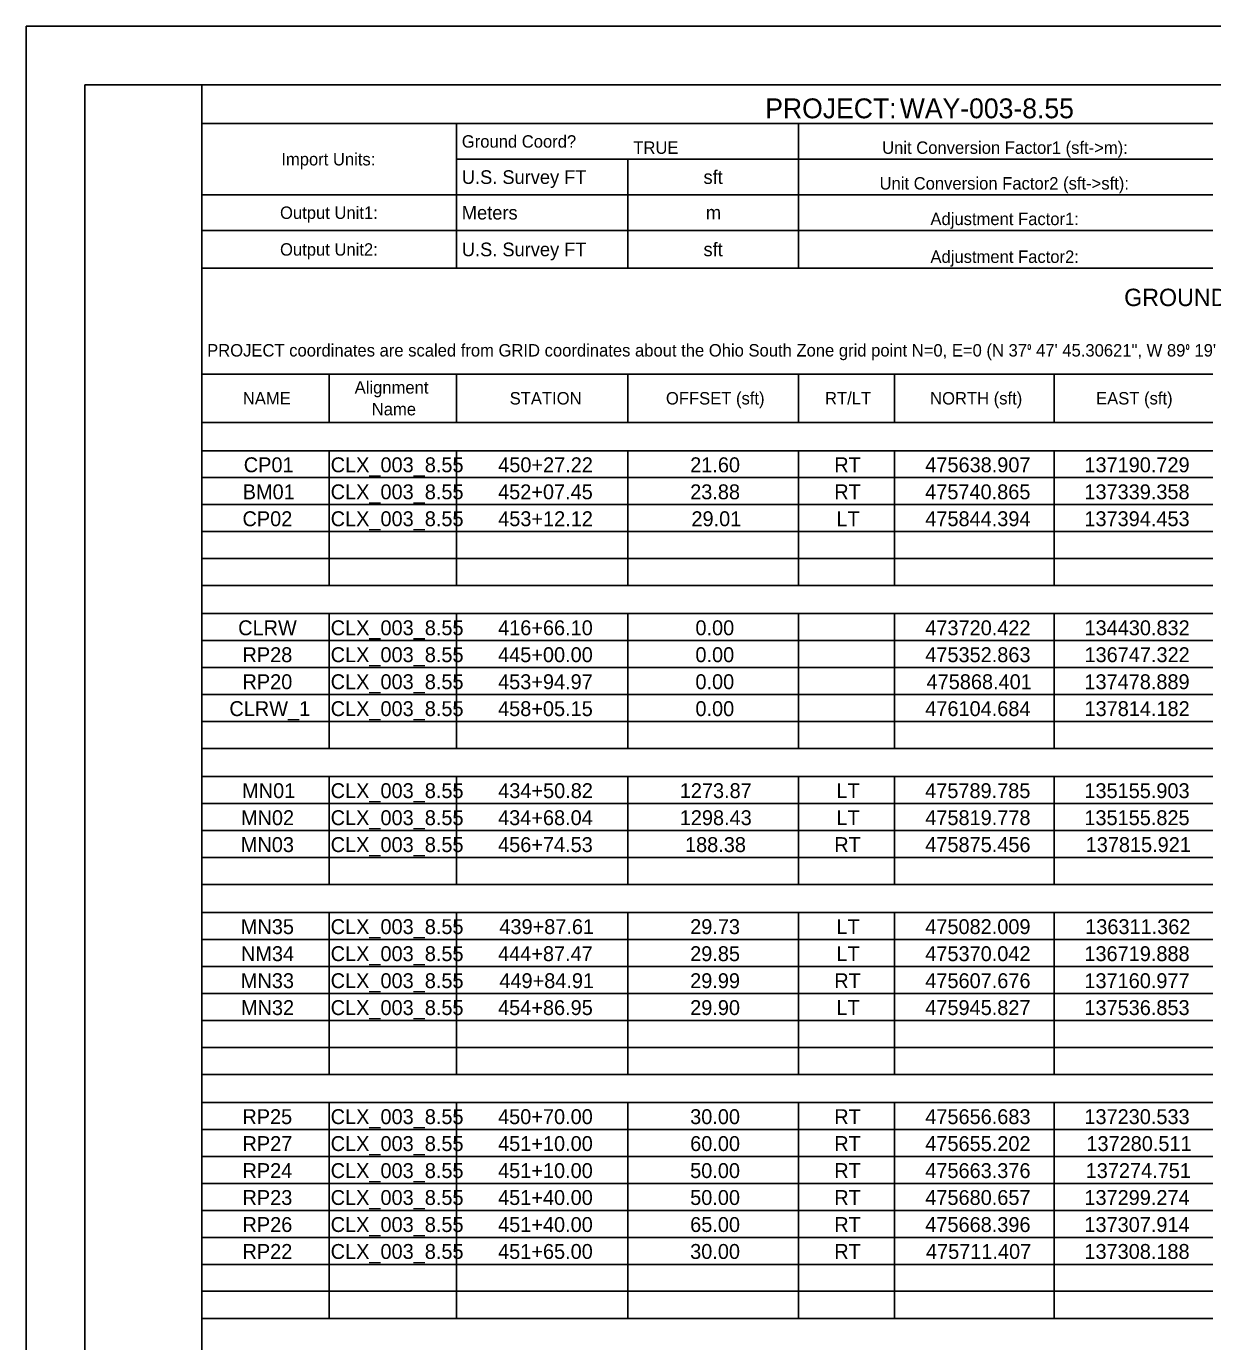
# Model space of a CAD drawing. Extents: x 0 to 34, y 0 to 22.
# Drawn here: x 0 to 10.14, y 10.76 to 22 of the extents above; entities that cross this region are included whole.
import ezdxf

# ---------------------------------------------------------------- set-up
doc = ezdxf.new("R2010")
doc.units = 0
for name, color, linetype in [('SH_Border', 7, 'Continuous'), ('SH_Cut_Line', 7, 'Continuous'), ('SH_Text', 7, 'Continuous')]:
    doc.layers.add(name, color=color, linetype=linetype)

msp = doc.modelspace()

# ---------------------------------------------------------------- linework, layer by layer
at = {"layer": 'SH_Border'}
for points in [[(0.5, 21.5), (1.5, 21.5), (1.5, 0.5), (0.5, 0.5)], [(1.5, 21.5), (33.5, 21.5), (33.5, 0.5), (1.5, 0.5)]]:
    msp.add_lwpolyline(points, close=True, dxfattribs=at)
at = {"layer": 'SH_Cut_Line'}
msp.add_lwpolyline([(0, 0), (34, 0), (34, 22), (0, 22)], close=True, dxfattribs=at)
at = {"layer": 'SH_Text'}
for p, q in [((1.5, 21.168), (10.142, 21.168)), ((1.5, 21.168), (1.5, 19.028)), ((3.677, 21.168), (3.677, 19.932)), ((6.6, 21.168), (6.6, 19.932)), ((3.677, 20.864), (10.142, 20.864)), ((5.143, 20.864), (5.143, 19.932)), ((1.5, 20.559), (6.6, 20.559)), ((6.6, 20.559), (10.142, 20.559)), ((1.5, 20.255), (10.142, 20.255)), ((1.5, 19.932), (6.6, 19.932)), ((6.6, 19.932), (10.142, 19.932)), ((1.5, 19.028), (10.142, 19.028)), ((1.5, 19.028), (1.5, 17.451)), ((2.588, 19.028), (2.588, 18.613)), ((3.677, 19.028), (3.677, 18.613)), ((5.143, 19.028), (5.143, 18.613)), ((6.6, 19.028), (6.6, 18.613)), ((7.421, 19.028), (7.421, 18.613)), ((8.786, 19.028), (8.786, 18.613)), ((1.5, 18.613), (10.142, 18.613)), ((1.5, 18.373), (10.142, 18.373)), ((2.588, 18.373), (2.588, 17.451)), ((3.677, 18.373), (3.677, 17.451)), ((5.143, 18.373), (5.143, 17.451)), ((6.6, 18.373), (6.6, 17.451)), ((7.421, 18.373), (7.421, 17.451)), ((8.786, 18.373), (8.786, 17.451)), ((1.5, 18.143), (10.142, 18.143)), ((1.5, 17.912), (10.142, 17.912)), ((1.5, 17.682), (10.142, 17.682)), ((1.5, 17.451), (10.142, 17.451)), ((1.5, 17.451), (1.5, 16.981)), ((2.588, 17.451), (2.588, 17.221)), ((3.677, 17.451), (3.677, 17.221)), ((5.143, 17.451), (5.143, 17.221)), ((6.6, 17.451), (6.6, 17.221)), ((7.421, 17.451), (7.421, 17.221)), ((8.786, 17.451), (8.786, 17.221)), ((1.5, 17.221), (10.142, 17.221)), ((1.5, 16.981), (10.142, 16.981)), ((1.5, 16.981), (1.5, 13.504)), ((2.588, 16.981), (2.588, 15.828)), ((3.677, 16.981), (3.677, 15.828)), ((5.143, 16.981), (5.143, 15.828)), ((6.6, 16.981), (6.6, 15.828)), ((7.421, 16.981), (7.421, 15.828)), ((8.786, 16.981), (8.786, 15.828)), ((1.5, 16.75), (10.142, 16.75)), ((1.5, 16.52), (10.142, 16.52)), ((1.5, 16.289), (10.142, 16.289)), ((1.5, 16.059), (10.142, 16.059)), ((1.5, 15.828), (10.142, 15.828)), ((1.5, 15.588), (10.142, 15.588)), ((2.588, 15.588), (2.588, 14.666)), ((3.677, 15.588), (3.677, 14.666)), ((5.143, 15.588), (5.143, 14.666)), ((6.6, 15.588), (6.6, 14.666)), ((7.421, 15.588), (7.421, 14.666)), ((8.786, 15.588), (8.786, 14.666)), ((1.5, 15.358), (10.142, 15.358)), ((1.5, 15.127), (10.142, 15.127)), ((1.5, 14.896), (10.142, 14.896)), ((1.5, 14.666), (10.142, 14.666)), ((1.5, 14.426), (10.142, 14.426)), ((2.588, 14.426), (2.588, 13.504)), ((3.677, 14.426), (3.677, 13.504)), ((5.143, 14.426), (5.143, 13.504)), ((6.6, 14.426), (6.6, 13.504)), ((7.421, 14.426), (7.421, 13.504)), ((8.786, 14.426), (8.786, 13.504)), ((1.5, 14.195), (10.142, 14.195)), ((1.5, 13.965), (10.142, 13.965)), ((1.5, 13.734), (10.142, 13.734)), ((1.5, 13.504), (10.142, 13.504)), ((1.5, 13.504), (1.5, 12.803)), ((2.588, 13.504), (2.588, 13.043)), ((3.677, 13.504), (3.677, 13.043)), ((5.143, 13.504), (5.143, 13.043)), ((6.6, 13.504), (6.6, 13.043)), ((7.421, 13.504), (7.421, 13.043)), ((8.786, 13.504), (8.786, 13.043)), ((1.5, 13.273), (10.142, 13.273)), ((1.5, 13.043), (10.142, 13.043)), ((1.5, 12.803), (10.142, 12.803)), ((1.5, 12.803), (1.5, 10.958)), ((2.588, 12.803), (2.588, 10.958)), ((3.677, 12.803), (3.677, 10.958)), ((5.143, 12.803), (5.143, 10.958)), ((6.6, 12.803), (6.6, 10.958)), ((7.421, 12.803), (7.421, 10.958)), ((8.786, 12.803), (8.786, 10.958)), ((1.5, 12.572), (10.142, 12.572)), ((1.5, 12.342), (10.142, 12.342)), ((1.5, 12.111), (10.142, 12.111)), ((1.5, 11.881), (10.142, 11.881)), ((1.5, 11.65), (10.142, 11.65)), ((1.5, 11.419), (10.142, 11.419)), ((1.5, 11.189), (10.142, 11.189)), ((1.5, 10.958), (10.142, 10.958))]:
    msp.add_line(p, q, dxfattribs=at)

# ---------------------------------------------------------------- texts
for s, height, p in [('PROJECT:', 0.1697, (6.317, 21.214)), ('WAY-003-8.55', 0.1697, (7.467, 21.214)), ('Ground Coord?', 0.10606, (3.723, 20.963)), ('Import Units:', 0.10606, (2.18, 20.811)), ('TRUE', 0.1061, (5.189, 20.91)), ('Unit Conversion Factor1 (sft->m):', 0.10606, (7.316, 20.91)), ('U.S. Survey FT', 0.11667, (3.723, 20.653)), ('sft', 0.1167, (5.789, 20.653)), ('Unit Conversion Factor2 (sft->sft):', 0.10606, (7.294, 20.605)), ('Output Unit1:', 0.10606, (2.169, 20.354)), ('Meters', 0.1167, (3.723, 20.349)), ('m', 0.117, (5.809, 20.349)), ('Adjustment Factor1:', 0.10606, (7.729, 20.301)), ('Output Unit2:', 0.10606, (2.169, 20.04)), ('U.S. Survey FT', 0.11667, (3.723, 20.035)), ('sft', 0.1167, (5.789, 20.035)), ('Adjustment Factor2:', 0.10606, (7.729, 19.978)), ('GROUND COORDINATES - U.S. Survey FT', 0.14849, (9.385, 19.609)), ('PROJECT coordinates are scaled from GRID coordinates about the Ohio South Zone grid point N=0, E=0 (N 37⁰ 47\' 45.30621", W 89⁰ 19\' 00.02517")', 0.106063, (1.546, 19.178)), ('Alignment ', 0.1061, (2.807, 18.861)), ('NAME', 0.1061, (1.851, 18.768)), ('Name', 0.1061, (2.953, 18.675)), ('STATION', 0.1061, (4.132, 18.768)), ('OFFSET (sft)', 0.10606, (5.468, 18.768)), ('RT/LT', 0.1061, (6.828, 18.768)), ('NORTH (sft)', 0.10606, (7.726, 18.768)), ('EAST (sft)', 0.1061, (9.145, 18.768)), ('CP01', 0.1273, (1.859, 18.189)), ('CLX_003_8.55', 0.12728, (2.602, 18.189)), ('450+27.22', 0.1273, (4.034, 18.189)), ('21.60', 0.1273, (5.675, 18.189)), ('RT', 0.1273, (6.907, 18.189)), ('475638.907', 0.1273, (7.685, 18.189)), ('137190.729', 0.1273, (9.045, 18.189)), ('BM01', 0.1273, (1.85, 17.958)), ('CLX_003_8.55', 0.12728, (2.602, 17.958)), ('452+07.45', 0.1273, (4.033, 17.958)), ('23.88', 0.1273, (5.675, 17.958)), ('RT', 0.1273, (6.907, 17.958)), ('475740.865', 0.1273, (7.684, 17.958)), ('137339.358', 0.1273, (9.045, 17.958)), ('CP02', 0.1273, (1.848, 17.728)), ('CLX_003_8.55', 0.12728, (2.602, 17.728)), ('453+12.12', 0.1273, (4.034, 17.728)), ('29.01', 0.1273, (5.686, 17.728)), ('LT', 0.1273, (6.925, 17.728)), ('475844.394', 0.1273, (7.685, 17.728)), ('137394.453', 0.1273, (9.045, 17.728)), ('CLRW', 0.1273, (1.811, 16.796)), ('CLX_003_8.55', 0.12728, (2.602, 16.796)), ('416+66.10', 0.1273, (4.033, 16.796)), ('0.00', 0.1273, (5.72, 16.796)), ('473720.422', 0.1273, (7.685, 16.796)), ('134430.832', 0.1273, (9.046, 16.796)), ('RP28', 0.1273, (1.848, 16.566)), ('CLX_003_8.55', 0.12728, (2.602, 16.566)), ('445+00.00', 0.1273, (4.033, 16.566)), ('0.00', 0.1273, (5.72, 16.566)), ('475352.863', 0.1273, (7.685, 16.566)), ('136747.322', 0.1273, (9.046, 16.566)), ('RP20', 0.1273, (1.848, 16.335)), ('CLX_003_8.55', 0.12728, (2.602, 16.335)), ('453+94.97', 0.1273, (4.033, 16.335)), ('0.00', 0.1273, (5.72, 16.335)), ('475868.401', 0.1273, (7.696, 16.335)), ('137478.889', 0.1273, (9.045, 16.335)), ('CLRW_1', 0.1273, (1.736, 16.105)), ('CLX_003_8.55', 0.12728, (2.602, 16.105)), ('458+05.15', 0.1273, (4.033, 16.105)), ('0.00', 0.1273, (5.72, 16.105)), ('476104.684', 0.1273, (7.685, 16.105)), ('137814.182', 0.1273, (9.046, 16.105)), ('MN01', 0.1273, (1.845, 15.404)), ('CLX_003_8.55', 0.12728, (2.602, 15.404)), ('434+50.82', 0.1273, (4.034, 15.404)), ('1273.87', 0.1273, (5.586, 15.404)), ('LT', 0.1273, (6.925, 15.404)), ('475789.785', 0.1273, (7.684, 15.404)), ('135155.903', 0.1273, (9.045, 15.404)), ('MN02', 0.1273, (1.835, 15.173)), ('CLX_003_8.55', 0.12728, (2.602, 15.173)), ('434+68.04', 0.1273, (4.033, 15.173)), ('1298.43', 0.1273, (5.586, 15.173)), ('LT', 0.1273, (6.925, 15.173)), ('475819.778', 0.1273, (7.685, 15.173)), ('135155.825', 0.1273, (9.045, 15.173)), ('MN03', 0.1273, (1.834, 14.943)), ('CLX_003_8.55', 0.12728, (2.602, 14.943)), ('456+74.53', 0.1273, (4.033, 14.943)), ('188.38', 0.1273, (5.631, 14.943)), ('RT', 0.1273, (6.907, 14.943)), ('475875.456', 0.1273, (7.685, 14.943)), ('137815.921', 0.1273, (9.056, 14.943)), ('MN35', 0.1273, (1.834, 14.242)), ('CLX_003_8.55', 0.12728, (2.602, 14.242)), ('439+87.61', 0.1273, (4.044, 14.242)), ('29.73', 0.1273, (5.675, 14.242)), ('LT', 0.1273, (6.925, 14.242)), ('475082.009', 0.1273, (7.685, 14.242)), ('136311.362', 0.1273, (9.052, 14.242)), ('NM34', 0.1273, (1.835, 14.011)), ('CLX_003_8.55', 0.12728, (2.602, 14.011)), ('444+87.47', 0.1273, (4.033, 14.011)), ('29.85', 0.1273, (5.675, 14.011)), ('LT', 0.1273, (6.925, 14.011)), ('475370.042', 0.1273, (7.685, 14.011)), ('136719.888', 0.1273, (9.045, 14.011)), ('MN33', 0.1273, (1.834, 13.78)), ('CLX_003_8.55', 0.12728, (2.602, 13.78)), ('449+84.91', 0.1273, (4.044, 13.78)), ('29.99', 0.1273, (5.675, 13.78)), ('RT', 0.1273, (6.907, 13.78)), ('475607.676', 0.1273, (7.685, 13.78)), ('137160.977', 0.1273, (9.045, 13.78)), ('MN32', 0.1273, (1.835, 13.55)), ('CLX_003_8.55', 0.12728, (2.602, 13.55)), ('454+86.95', 0.1273, (4.033, 13.55)), ('29.90', 0.1273, (5.675, 13.55)), ('LT', 0.1273, (6.925, 13.55)), ('475945.827', 0.1273, (7.685, 13.55)), ('137536.853', 0.1273, (9.045, 13.55)), ('RP25', 0.1273, (1.847, 12.618)), ('CLX_003_8.55', 0.12728, (2.602, 12.618)), ('450+70.00', 0.1273, (4.033, 12.618)), ('30.00', 0.1273, (5.675, 12.618)), ('RT', 0.1273, (6.907, 12.618)), ('475656.683', 0.1273, (7.685, 12.618)), ('137230.533', 0.1273, (9.045, 12.618)), ('RP27', 0.1273, (1.848, 12.388)), ('CLX_003_8.55', 0.12728, (2.602, 12.388)), ('451+10.00', 0.1273, (4.033, 12.388)), ('60.00', 0.1273, (5.675, 12.388)), ('RT', 0.1273, (6.907, 12.388)), ('475655.202', 0.1273, (7.685, 12.388)), ('137280.511', 0.1273, (9.062, 12.388)), ('RP24', 0.1273, (1.848, 12.157)), ('CLX_003_8.55', 0.12728, (2.602, 12.157)), ('451+10.00', 0.1273, (4.033, 12.157)), ('50.00', 0.1273, (5.675, 12.157)), ('RT', 0.1273, (6.907, 12.157)), ('475663.376', 0.1273, (7.685, 12.157)), ('137274.751', 0.1273, (9.056, 12.157)), ('RP23', 0.1273, (1.848, 11.927)), ('CLX_003_8.55', 0.12728, (2.602, 11.927)), ('451+40.00', 0.1273, (4.033, 11.927)), ('50.00', 0.1273, (5.675, 11.927)), ('RT', 0.1273, (6.907, 11.927)), ('475680.657', 0.1273, (7.685, 11.927)), ('137299.274', 0.1273, (9.045, 11.927)), ('RP26', 0.1273, (1.848, 11.696)), ('CLX_003_8.55', 0.12728, (2.602, 11.696)), ('451+40.00', 0.1273, (4.033, 11.696)), ('65.00', 0.1273, (5.675, 11.696)), ('RT', 0.1273, (6.907, 11.696)), ('475668.396', 0.1273, (7.685, 11.696)), ('137307.914', 0.1273, (9.045, 11.696)), ('RP22', 0.1273, (1.848, 11.466)), ('CLX_003_8.55', 0.12728, (2.602, 11.466)), ('451+65.00', 0.1273, (4.033, 11.466)), ('30.00', 0.1273, (5.675, 11.466)), ('RT', 0.1273, (6.907, 11.466)), ('475711.407', 0.1273, (7.691, 11.466)), ('137308.188', 0.1273, (9.045, 11.466))]:
    msp.add_text(s, height=height, dxfattribs=at).set_placement(p)

doc.saveas('drawing.dxf')
